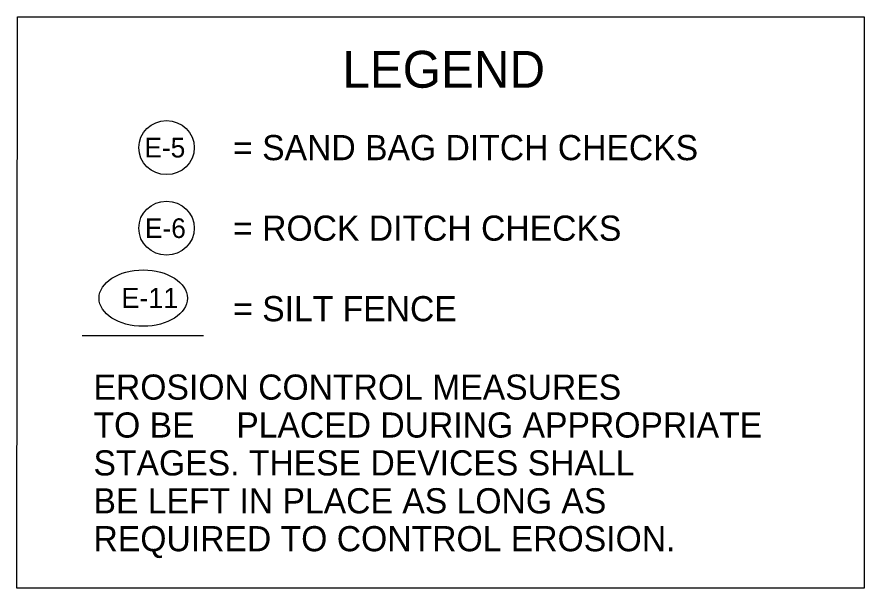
# Model space of a CAD drawing. Extents: x 1405136 to 1406586, y 1842078 to 1843486.
# Drawn here: x 1406375.6 to 1406585.8, y 1843344.1 to 1843485.9 of the extents above; entities that cross this region are included whole.
import ezdxf

# ---------------------------------------------------------------- set-up
doc = ezdxf.new("R2010")
doc.units = 0
doc.layers.add('X_ARROWS_LEGEND', color=7, linetype='Continuous')

msp = doc.modelspace()

# ---------------------------------------------------------------- linework, layer by layer
at = {"layer": 'X_ARROWS_LEGEND'}
for p, q in [((1406375.59, 1843344.08), (1406375.72, 1843485.9)), ((1406375.59, 1843344.08), (1406375.72, 1843485.9)), ((1406375.59, 1843344.08), (1406375.72, 1843485.9)), ((1406375.72, 1843485.9), (1406585.82, 1843485.9)), ((1406375.72, 1843485.9), (1406585.82, 1843485.9)), ((1406375.72, 1843485.9), (1406585.82, 1843485.9)), ((1406585.82, 1843485.9), (1406585.82, 1843344.08)), ((1406585.82, 1843485.9), (1406585.82, 1843344.08)), ((1406585.82, 1843485.9), (1406585.82, 1843344.08)), ((1406585.82, 1843344.08), (1406375.59, 1843344.08)), ((1406585.82, 1843344.08), (1406375.59, 1843344.08)), ((1406585.82, 1843344.08), (1406375.59, 1843344.08))]:
    msp.add_line(p, q, dxfattribs=at)
msp.add_lwpolyline([(1406391.76, 1843406.78), (1406421.88, 1843406.79)], dxfattribs=at)
msp.add_lwpolyline([(1406391.76, 1843406.78), (1406421.88, 1843406.79)], dxfattribs=at)
msp.add_lwpolyline([(1406391.76, 1843406.78), (1406421.88, 1843406.79)], dxfattribs=at)
for centre, major_axis, ratio in [((1406412.71, 1843453.45), (-6.88, 0), 0.97521), ((1406412.71, 1843453.45), (-6.88, 0), 0.97521), ((1406412.71, 1843453.45), (-6.88, 0), 0.97521), ((1406412.71, 1843433.45), (-6.88, 0), 0.97521), ((1406412.71, 1843433.45), (-6.88, 0), 0.97521), ((1406412.71, 1843433.45), (-6.88, 0), 0.97521), ((1406406.92, 1843416.08), (10.96, 0), 0.638788), ((1406406.92, 1843416.08), (10.96, 0), 0.638788), ((1406406.92, 1843416.08), (10.96, 0), 0.638788)]:
    msp.add_ellipse(centre, major_axis=major_axis, ratio=ratio, dxfattribs=at)

# ---------------------------------------------------------------- texts
for s, height, rotation, p in [('LEGEND', 9.143, 0, (1406456.37, 1843468.33)), ('LEGEND', 9.143, 0, (1406456.37, 1843468.33)), ('LEGEND', 9.143, 0, (1406456.37, 1843468.33)), ('E-5', 4.876, 0, (1406407.22, 1843451.01)), ('E-5', 4.876, 0, (1406407.22, 1843451.01)), ('E-5', 4.876, 0, (1406407.22, 1843451.01)), ('= SAND BAG DITCH CHECKS', 6.25, 0, (1406429.24, 1843450.33)), ('= SAND BAG DITCH CHECKS', 6.25, 0, (1406429.24, 1843450.33)), ('= SAND BAG DITCH CHECKS', 6.25, 0, (1406429.24, 1843450.33)), ('= ROCK DITCH CHECKS', 6.25, 0, (1406429.24, 1843430.33)), ('= ROCK DITCH CHECKS', 6.25, 0, (1406429.24, 1843430.33)), ('= ROCK DITCH CHECKS', 6.25, 0, (1406429.24, 1843430.33)), ('E-6', 4.876, 0, (1406407.36, 1843431.01)), ('E-6', 4.876, 0, (1406407.36, 1843431.01)), ('E-6', 4.876, 0, (1406407.36, 1843431.01)), ('E-11', 4.999, 360, (1406401.51, 1843413.62)), ('E-11', 4.999, 360, (1406401.51, 1843413.62)), ('E-11', 4.999, 360, (1406401.51, 1843413.62)), ('= SILT FENCE', 6.25, 0, (1406429.25, 1843410.33)), ('= SILT FENCE', 6.25, 0, (1406429.25, 1843410.33)), ('= SILT FENCE', 6.25, 0, (1406429.25, 1843410.33)), ('EROSION CONTROL MEASURES', 6.25, 0, (1406394.59, 1843390.86)), ('EROSION CONTROL MEASURES', 6.25, 0, (1406394.59, 1843390.86)), ('EROSION CONTROL MEASURES', 6.25, 0, (1406394.59, 1843390.86)), ('TO BE ', 6.25, 0, (1406394.59, 1843381.45)), ('TO BE ', 6.25, 0, (1406394.59, 1843381.45)), ('TO BE ', 6.25, 0, (1406394.59, 1843381.45)), ('PLACED DURING APPROPRIATE', 6.25, 0, (1406430.02, 1843381.45)), ('PLACED DURING APPROPRIATE', 6.25, 0, (1406430.02, 1843381.45)), ('PLACED DURING APPROPRIATE', 6.25, 0, (1406430.02, 1843381.45)), ('STAGES. THESE DEVICES SHALL', 6.25, 0, (1406394.59, 1843372.04)), ('STAGES. THESE DEVICES SHALL', 6.25, 0, (1406394.59, 1843372.04)), ('STAGES. THESE DEVICES SHALL', 6.25, 0, (1406394.59, 1843372.04)), ('BE LEFT IN PLACE AS LONG AS', 6.25, 0, (1406394.59, 1843362.63)), ('BE LEFT IN PLACE AS LONG AS', 6.25, 0, (1406394.59, 1843362.63)), ('BE LEFT IN PLACE AS LONG AS', 6.25, 0, (1406394.59, 1843362.63)), ('REQUIRED TO CONTROL EROSION.', 6.25, 0, (1406394.59, 1843353.22)), ('REQUIRED TO CONTROL EROSION.', 6.25, 0, (1406394.59, 1843353.22)), ('REQUIRED TO CONTROL EROSION.', 6.25, 0, (1406394.59, 1843353.22))]:
    msp.add_text(s, height=height, rotation=rotation, dxfattribs=at).set_placement(p)

doc.saveas('drawing.dxf')
